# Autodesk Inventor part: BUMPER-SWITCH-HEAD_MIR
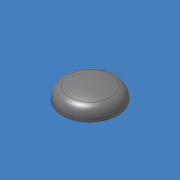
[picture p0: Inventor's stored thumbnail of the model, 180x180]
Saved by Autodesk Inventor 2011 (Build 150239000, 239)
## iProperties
Created: 2007-08
Part Number: BUMPER-SWITCH-HEAD_MIR
Material: ABS Plastic
Document SubType Name: Modeling
Density: 1.06 g/cm^3
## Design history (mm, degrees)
derived "BUMPER-SWITCH-HEAD.ipt"
body "Solid1"
tag "TaggingFeature2"
feature "DerivedBody::BUMPER-SWITCH-HEAD.ipt" dims "d0" = 10
